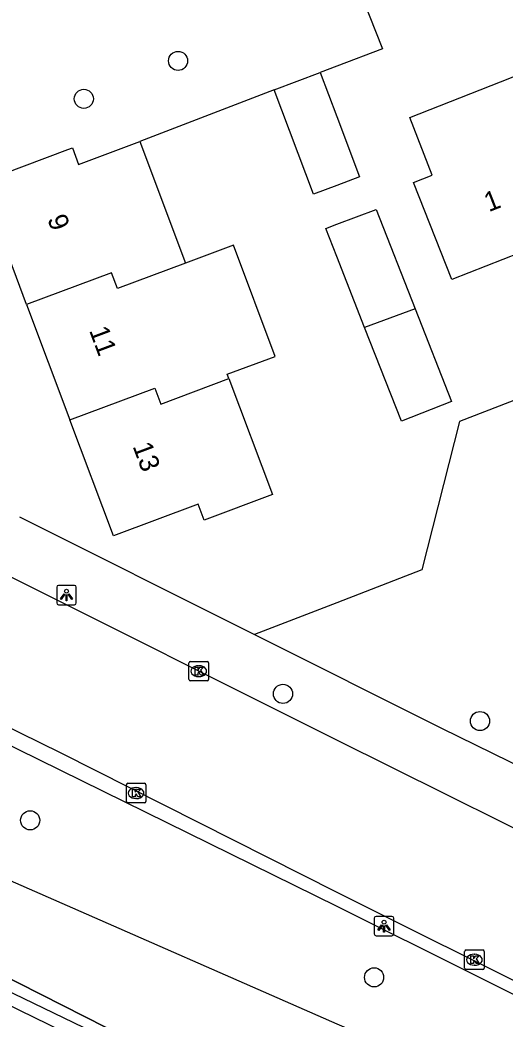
# Model space of a CAD drawing. Extents: x 162990 to 165007, y 383433 to 384336.
# Drawn here: x 163983.8 to 164008.6, y 383788.8 to 383839.9 of the extents above; entities that cross this region are included whole.
import ezdxf

# ---------------------------------------------------------------- set-up
doc = ezdxf.new("R2010")
doc.units = 0
for name, color, linetype in [('IMGEO_Boom', 7, 'Continuous'), ('IMGEO_Geluidsscherm', 7, 'Continuous'), ('IMGEO_Groenvoorziening', 7, 'Continuous'), ('IMGEO_Kolk', 7, 'Continuous'), ('IMGEO_Lichtpunt', 7, 'Continuous'), ('IMGEO_Pand', 7, 'Continuous'), ('IMGEO_Pand_nummerreeks', 7, 'Continuous'), ('IMGEO_Rijbaan_lokaal_open', 7, 'Continuous'), ('IMGEO_Spoorbaan_halfverhard', 7, 'Continuous'), ('IMGEO_Voetpad_open', 7, 'Continuous')]:
    doc.layers.add(name, color=color, linetype=linetype)

msp = doc.modelspace()

# ---------------------------------------------------------------- linework, layer by layer
at = {"layer": 'IMGEO_Boom'}
for centre in [(163991.875, 383837.819), (163987.051, 383835.877), (163997.247, 383805.404), (164007.333, 383804.011), (163984.304, 383798.928), (164001.912, 383790.887)]:
    msp.add_circle(centre, 0.489, dxfattribs=at)
at = {"layer": 'IMGEO_Geluidsscherm'}
msp.add_lwpolyline([(163949.283, 383805.578), (163958.493, 383801.554), (163976.899, 383793.724), (163981.48, 383791.723), (163994.879, 383784.928), (164003.875, 383780.639), (164032.407, 383767.008), (164041.418, 383762.706), (164050.208, 383757.972), (164059.111, 383753.358), (164067.978, 383748.728), (164076.812, 383744.138)], dxfattribs=at)
at = {"layer": 'IMGEO_Groenvoorziening'}
msp.add_lwpolyline([(163762.901, 383879.022), (163763.142, 383879.783), (163770.57, 383877.207), (163786.519, 383872.073), (163829.229, 383857.865), (163846.299, 383851.794), (163880.237, 383839.724), (163923.817, 383821.246), (163935.03, 383816.871), (163938.07, 383815.685), (164000, 383788.515), (164001.434, 383787.886), (164020.113, 383778.24), (164032.955, 383772.178), (164060.575, 383757.962), (164061.832, 383760.603)], dxfattribs=at)
at = {"layer": 'IMGEO_Kolk'}
for p, q in [((163992.435, 383806.142), (163992.435, 383806.994)), ((163992.51, 383807.068), (163993.362, 383807.068)), ((163993.436, 383806.994), (163993.436, 383806.142)), ((163992.923, 383806.848), (163992.948, 383806.848)), ((163993.362, 383806.068), (163992.51, 383806.068)), ((163992.946, 383806.288), (163992.921, 383806.288)), ((163989.229, 383799.899), (163989.229, 383800.751)), ((163989.304, 383800.825), (163990.156, 383800.825)), ((163989.717, 383800.605), (163989.742, 383800.605)), ((163990.23, 383800.751), (163990.23, 383799.899)), ((163990.156, 383799.825), (163989.304, 383799.825)), ((163989.74, 383800.045), (163989.715, 383800.045)), ((164006.548, 383791.363), (164006.548, 383792.215)), ((164006.623, 383792.289), (164007.475, 383792.289)), ((164007.549, 383792.215), (164007.549, 383791.363)), ((164007.036, 383792.069), (164007.061, 383792.069)), ((164007.475, 383791.289), (164006.623, 383791.289)), ((164007.059, 383791.509), (164007.034, 383791.509))]:
    msp.add_line(p, q, dxfattribs=at)
for points in [[(163992.435, 383806.142), (163992.435, 383806.994)], [(163992.51, 383807.068), (163993.362, 383807.068)], [(163993.436, 383806.994), (163993.436, 383806.142)], [(163992.756, 383806.768), (163992.879, 383806.768), (163992.879, 383806.617), (163993.009, 383806.768), (163993.173, 383806.768), (163993.027, 383806.617), (163993.18, 383806.368), (163993.028, 383806.368), (163992.943, 383806.532), (163992.879, 383806.465), (163992.879, 383806.368), (163992.756, 383806.368), (163992.756, 383806.768)], [(163993.362, 383806.068), (163992.51, 383806.068)], [(163989.229, 383799.899), (163989.229, 383800.751)], [(163989.304, 383800.825), (163990.156, 383800.825)], [(163989.55, 383800.525), (163989.673, 383800.525), (163989.673, 383800.374), (163989.803, 383800.525), (163989.967, 383800.525), (163989.821, 383800.374), (163989.974, 383800.125), (163989.822, 383800.125), (163989.737, 383800.289), (163989.673, 383800.222), (163989.673, 383800.125), (163989.55, 383800.125), (163989.55, 383800.525)], [(163990.23, 383800.751), (163990.23, 383799.899)], [(163990.156, 383799.825), (163989.304, 383799.825)], [(164006.548, 383791.363), (164006.548, 383792.215)], [(164006.623, 383792.289), (164007.475, 383792.289)], [(164007.549, 383792.215), (164007.549, 383791.363)], [(164006.869, 383791.989), (164006.992, 383791.989), (164006.992, 383791.838), (164007.122, 383791.989), (164007.286, 383791.989), (164007.14, 383791.838), (164007.293, 383791.589), (164007.141, 383791.589), (164007.056, 383791.753), (164006.992, 383791.686), (164006.992, 383791.589), (164006.869, 383791.589), (164006.869, 383791.989)], [(164007.475, 383791.289), (164006.623, 383791.289)]]:
    msp.add_lwpolyline(points, dxfattribs=at)
for centre, start, end in [((163992.512, 383806.992), 91.552, 178.448), ((163992.512, 383806.992), 91.552, 178.448), ((163993.36, 383806.992), 1.552, 88.448), ((163993.36, 383806.992), 1.552, 88.448), ((163992.512, 383806.144), 181.552, 268.448), ((163992.512, 383806.144), 181.552, 268.448), ((163993.36, 383806.144), 271.552, 358.448), ((163993.36, 383806.144), 271.552, 358.448), ((163989.306, 383800.749), 91.552, 178.448), ((163989.306, 383800.749), 91.552, 178.448), ((163990.154, 383800.749), 1.552, 88.448), ((163990.154, 383800.749), 1.552, 88.448), ((163989.306, 383799.901), 181.552, 268.448), ((163989.306, 383799.901), 181.552, 268.448), ((163990.154, 383799.901), 271.552, 358.448), ((163990.154, 383799.901), 271.552, 358.448), ((164006.625, 383792.213), 91.552, 178.448), ((164006.625, 383792.213), 91.552, 178.448), ((164007.473, 383792.213), 1.552, 88.448), ((164007.473, 383792.213), 1.552, 88.448), ((164006.625, 383791.365), 181.552, 268.448), ((164006.625, 383791.365), 181.552, 268.448), ((164007.473, 383791.365), 271.552, 358.448), ((164007.473, 383791.365), 271.552, 358.448)]:
    msp.add_arc(centre, 0.0765, start, end, dxfattribs=at)
for centre, major_axis, ratio, start_param, end_param in [((163992.922, 383806.568), (-0.387, 0.002), 0.722429, 4.712389, 7.853982), ((163992.947, 383806.568), (-0.39, 0.002), 0.717154, 1.570796, 4.712389), ((163989.716, 383800.325), (-0.387, 0.002), 0.722429, 4.712389, 7.853982), ((163989.741, 383800.325), (-0.39, 0.002), 0.717154, 1.570796, 4.712389), ((164007.035, 383791.789), (-0.387, 0.002), 0.722429, 4.712389, 7.853982), ((164007.06, 383791.789), (-0.39, 0.002), 0.717154, 1.570796, 4.712389)]:
    msp.add_ellipse(centre, major_axis=major_axis, ratio=ratio, start_param=start_param, end_param=end_param, dxfattribs=at)
at = {"layer": 'IMGEO_Lichtpunt'}
for p, q in [((163985.665, 383810.867), (163985.665, 383810.06)), ((163985.665, 383810.867), (163985.665, 383810.06)), ((163986.567, 383810.962), (163985.759, 383810.962)), ((163986.567, 383810.962), (163985.759, 383810.962)), ((163986.661, 383810.06), (163986.661, 383810.867)), ((163986.661, 383810.06), (163986.661, 383810.867)), ((163985.759, 383809.966), (163986.567, 383809.966)), ((163985.759, 383809.966), (163986.567, 383809.966)), ((164001.923, 383793.915), (164001.923, 383793.108)), ((164001.923, 383793.915), (164001.923, 383793.108)), ((164002.825, 383794.01), (164002.017, 383794.01)), ((164002.825, 383794.01), (164002.017, 383794.01)), ((164002.919, 383793.108), (164002.919, 383793.915)), ((164002.919, 383793.108), (164002.919, 383793.915)), ((164002.017, 383793.014), (164002.825, 383793.014)), ((164002.017, 383793.014), (164002.825, 383793.014))]:
    msp.add_line(p, q, dxfattribs=at)
for points in [[(163986.039, 383810.531), (163986.078, 383810.503), (163985.89, 383810.241), (163985.852, 383810.268), (163986.039, 383810.531)], [(163986.141, 383810.483), (163986.188, 383810.483), (163986.188, 383810.161), (163986.141, 383810.161), (163986.141, 383810.483)], [(163986.251, 383810.503), (163986.289, 383810.53), (163986.476, 383810.268), (163986.437, 383810.24), (163986.251, 383810.503)], [(164002.297, 383793.579), (164002.336, 383793.551), (164002.148, 383793.289), (164002.11, 383793.316), (164002.297, 383793.579)], [(164002.399, 383793.531), (164002.446, 383793.531), (164002.446, 383793.209), (164002.399, 383793.209), (164002.399, 383793.531)], [(164002.509, 383793.551), (164002.547, 383793.578), (164002.734, 383793.316), (164002.695, 383793.288), (164002.509, 383793.551)]]:
    msp.add_lwpolyline(points, dxfattribs=at)
for centre in [(163986.164, 383810.665), (164002.422, 383793.713)]:
    msp.add_circle(centre, 0.0994, dxfattribs=at)
for centre, start, end in [((163985.759, 383810.867), 90, 180), ((163985.759, 383810.867), 90, 180), ((163986.567, 383810.867), 0, 90), ((163986.567, 383810.867), 0, 90), ((163985.759, 383810.06), 180, 270), ((163985.759, 383810.06), 180, 270), ((163986.567, 383810.06), 270, 0), ((163986.567, 383810.06), 270, 360), ((164002.017, 383793.915), 90, 180), ((164002.017, 383793.915), 90, 180), ((164002.825, 383793.915), 0, 90), ((164002.825, 383793.915), 0, 90), ((164002.017, 383793.108), 180, 270), ((164002.017, 383793.108), 180, 270), ((164002.825, 383793.108), 270, 0), ((164002.825, 383793.108), 270, 360)]:
    msp.add_arc(centre, 0.0946, start, end, dxfattribs=at)
at = {"layer": 'IMGEO_Pand'}
for points in [[(163996.803, 383836.335), (163999.153, 383837.217)], [(163999.153, 383837.217), (164000, 383834.975), (164001.172, 383831.873), (164000, 383831.435), (163998.808, 383830.99), (163996.803, 383836.335)], [(164011.987, 383829.01), (164005.89, 383826.618), (164003.937, 383831.595), (164004.892, 383831.97), (164003.733, 383834.926), (164008.388, 383836.753), (164009.721, 383837.276)], [(163981.773, 383831.611), (163986.229, 383833.282), (163986.466, 383833.371), (163986.785, 383832.52), (163989.924, 383833.697)], [(163989.924, 383833.697), (163992.26, 383827.468)], [(163984.123, 383825.346), (163981.773, 383831.611)], [(164001.428, 383824.16), (164000, 383827.798), (163999.434, 383829.24), (164000, 383829.453), (164002.012, 383830.212), (164004.007, 383825.128)], [(163994.479, 383821.552), (163994.397, 383821.77), (163996.845, 383822.689), (163994.705, 383828.386), (163992.26, 383827.468)], [(163992.26, 383827.468), (163988.769, 383826.157), (163988.464, 383826.972), (163984.123, 383825.346)], [(163984.123, 383825.346), (163986.341, 383819.431)], [(164004.007, 383825.128), (164001.428, 383824.16)], [(164004.007, 383825.128), (164005.871, 383820.379), (164003.306, 383819.373), (164001.428, 383824.16)], [(163994.479, 383821.552), (163996.707, 383815.613), (163993.217, 383814.304), (163992.91, 383815.122), (163988.568, 383813.494), (163986.341, 383819.431)], [(163986.341, 383819.431), (163990.683, 383821.057), (163990.988, 383820.242), (163994.479, 383821.552)]]:
    msp.add_lwpolyline(points, dxfattribs=at)
at = {"layer": 'IMGEO_Rijbaan_lokaal_open'}
for points in [[(164014.159, 383795.997), (164000, 383803.041), (163982.59, 383811.732), (163970.395, 383817.873), (163963.039, 383821.502), (163961.404, 383822.3)], [(163958.238, 383815.976), (163985.881, 383802.377), (164000, 383795.245), (164011.05, 383789.744)]]:
    msp.add_lwpolyline(points, dxfattribs=at)
at = {"layer": 'IMGEO_Spoorbaan_halfverhard'}
for points in [[(164077.684, 383742.488), (164059.94, 383751.749), (164051.043, 383756.375), (164045.14, 383759.453), (164041.199, 383761.517), (164038.137, 383763.014), (164033.951, 383764.976), (164025.857, 383768.926), (164012.376, 383775.387), (164004.24, 383779.303), (163996.798, 383782.931), (163991.309, 383785.51), (163982.226, 383789.942), (163977.16, 383792.386), (163969.396, 383795.642), (163962.74, 383798.552), (163954.392, 383802.188), (163937.097, 383809.758)], [(163941.579, 383808.498), (163952.354, 383803.787), (163959.247, 383800.759), (163967.89, 383797.013), (163973.447, 383794.602), (163977.32, 383792.995), (163981.38, 383791.05), (163989.6, 383787.092), (164000.088, 383781.967), (164012.461, 383776.047), (164027.836, 383768.672), (164034.856, 383765.255), (164038.873, 383763.39), (164042.324, 383761.623), (164050.773, 383757.225), (164058.642, 383753.14), (164065.81, 383749.41), (164078.944, 383742.585)], [(164076.812, 383744.138), (164067.978, 383748.728), (164059.111, 383753.358), (164050.208, 383757.972), (164041.418, 383762.706), (164032.407, 383767.008), (164003.875, 383780.639), (163994.879, 383784.928), (163981.48, 383791.723), (163976.899, 383793.724), (163958.493, 383801.554), (163949.283, 383805.578)]]:
    msp.add_lwpolyline(points, dxfattribs=at)
at = {"layer": 'IMGEO_Voetpad_open'}
for points in [[(164000.366, 383843.452), (164002.349, 383838.439), (164000, 383837.541), (163999.153, 383837.217)], [(163996.803, 383836.335), (163989.924, 383833.697)], [(164011.927, 383821.53), (164006.276, 383819.348), (164004.357, 383811.748), (164000, 383810.058), (163995.788, 383808.444)], [(163952.06, 383818.131), (164000, 383794.524), (164063.019, 383763.095)], [(163983.75, 383814.472), (163995.474, 383808.601), (163995.788, 383808.444)], [(163995.788, 383808.444), (164005.358, 383803.649), (164021.968, 383795.511)]]:
    msp.add_lwpolyline(points, dxfattribs=at)

# ---------------------------------------------------------------- texts
at = {"layer": 'IMGEO_Pand_nummerreeks'}
for s, rotation, p in [('1', 21.4265, (164007.783, 383830.068)), ('9', 290.5592, (163985.169, 383829.735)), ('11', 290.5575, (163987.311, 383824.02)), ('13', 290.5592, (163989.537, 383818.087))]:
    msp.add_text(s, height=1, rotation=rotation, dxfattribs=at).set_placement(p)

doc.saveas('drawing.dxf')
